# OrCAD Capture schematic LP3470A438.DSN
size A; title: LP3470A Reset Voltage Supervisor; rev: 1.0; note: Datasheet:   SNVSBF5
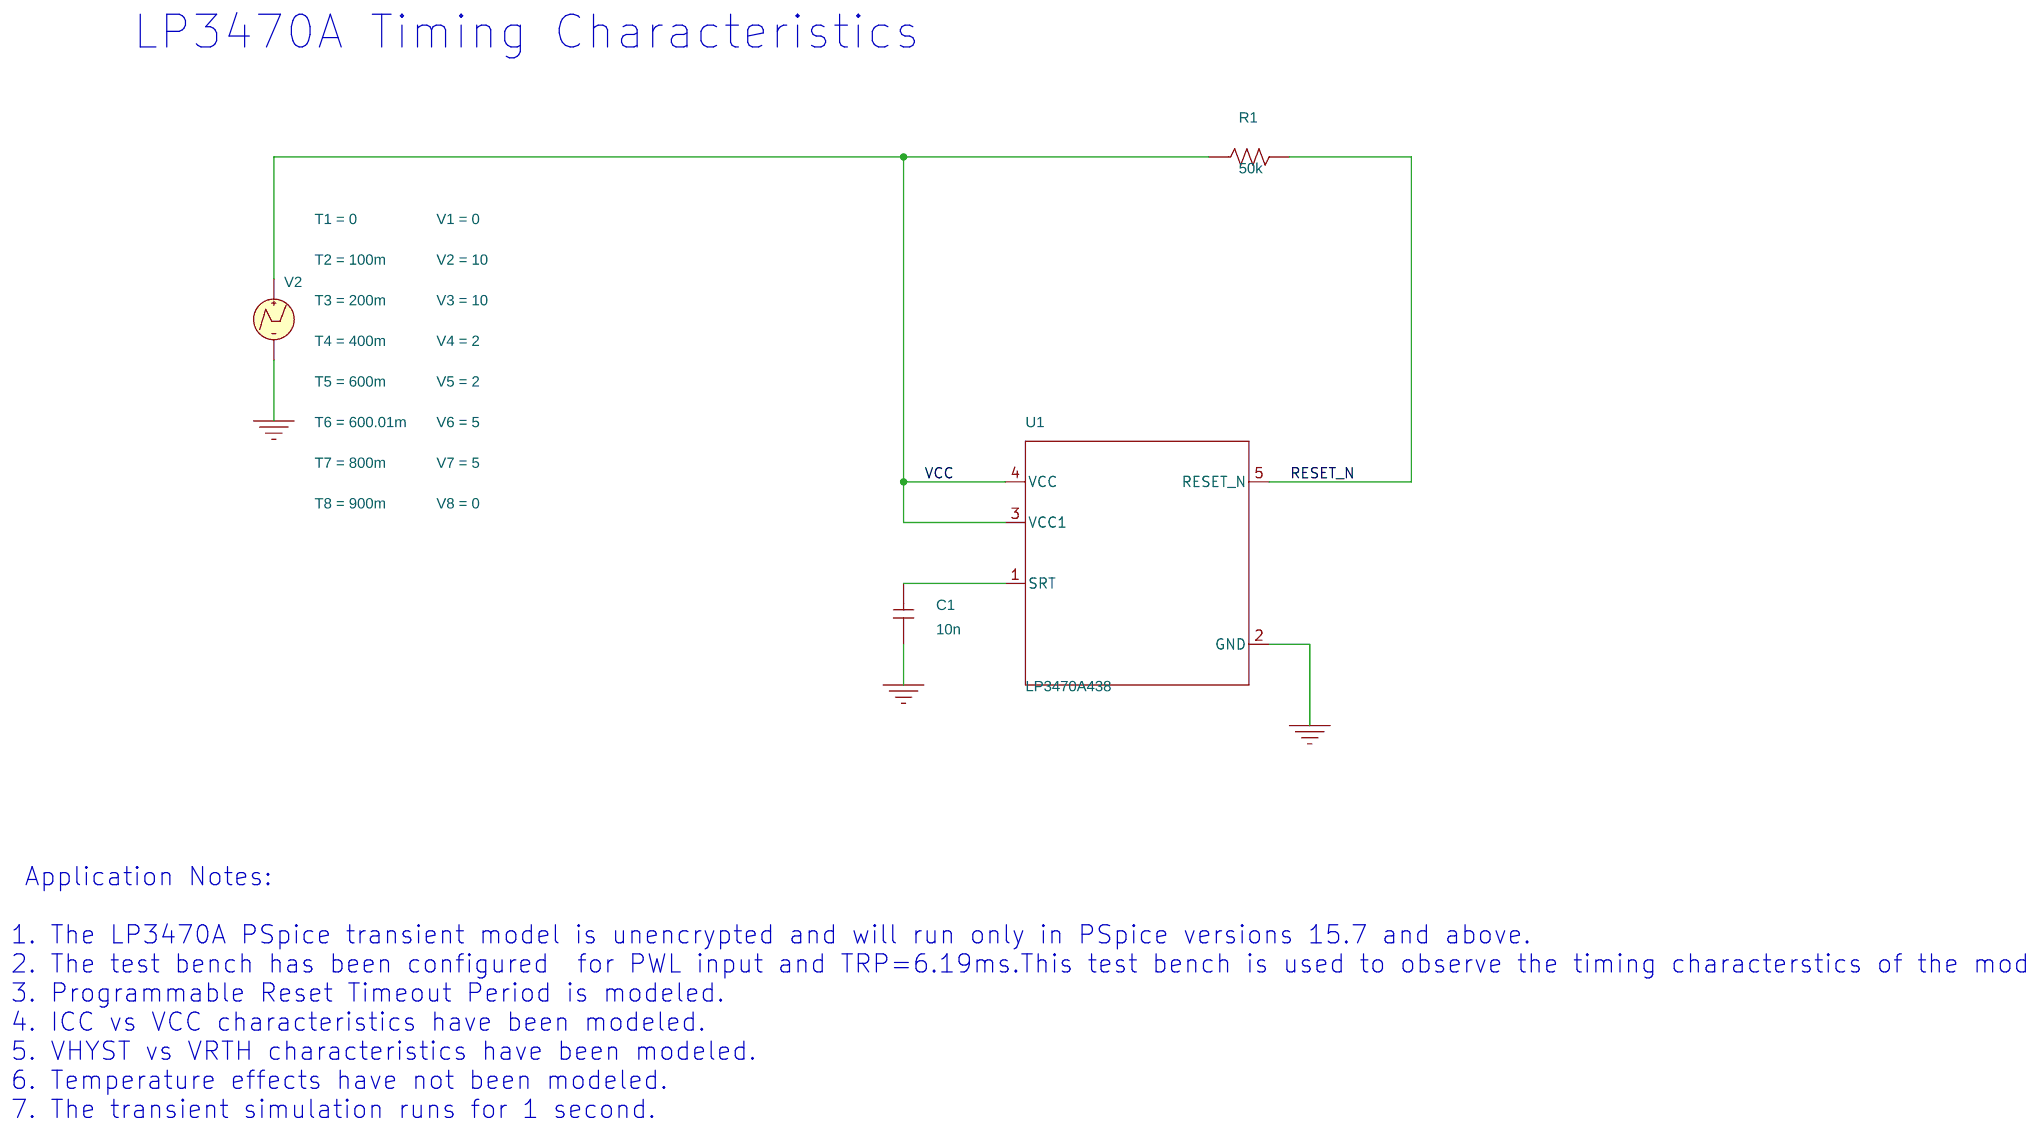
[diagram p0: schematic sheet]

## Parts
C1  10n  [RAD/CK05]
R1  50k  [AX/RC05]
U1  LP3470A438
V2  VPWL

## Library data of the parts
C1 = C
R1 = R
U1 = LP3470_TRANS
V2 = VPWL: PSpiceTemplate: V^@REFDES %+ %- ?DC|DC @DC| ?AC|AC @AC|\n+PWL @T1 @V1 @T2 @V2 #T3/@T3 @V3/ #T4/@T4 @V4/ #T5/@T5 @V5/ #T6/@T6 @V6/ #T7/@T7 @V7/ #T8/@T8 @V8/ #T9/@T9 @V9/ #T10/@T10 @V10/; T1: 0; T2: 100m; T3: 200m; T4: 400m; T5: 600m; T6: 600.01m; T7: 800m; T8: 900m; V1: 0; V2: 10; V3: 10; V4: 2; V5: 2; V6: 5; V7: 5; V8: 0

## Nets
VCC: R1.1 U1.3(VCC1) U1.4(VCC) V2.1(+)
0: C1.1 U1.2(GND) V2.2(-)
RESET_N: R1.2 U1.5(RESET_N)
N14961828: C1.2 U1.1(SRT)

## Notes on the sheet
- LP3470A Timing Characteristics
- Application Notes:
  1. The LP3470A PSpice transient model is unencrypted and will run only in PSpice versions 15.7 and above.
  2. The test bench has been configured  for PWL input and TRP=6.19ms.This test bench is used to observe the timing characterstics of the model.
  3. Programmable Reset Timeout Period is modeled.
  4. ICC vs VCC characteristics have been modeled.
  5. VHYST vs VRTH characteristics have been modeled.
  6. Temperature effects have not been modeled.
  7. The transient simulation runs for 1 second.
